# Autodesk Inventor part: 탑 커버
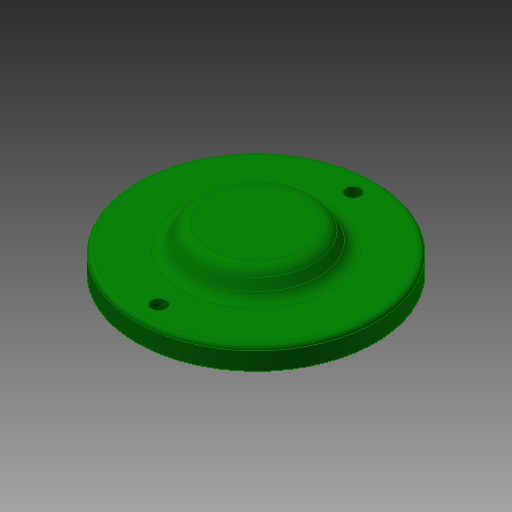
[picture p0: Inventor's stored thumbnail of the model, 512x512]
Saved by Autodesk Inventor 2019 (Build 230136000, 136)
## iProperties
Created: 2017-05
Part Number: 탑 커버
Material: 알루미늄 6061
Document SubType Name: Modeling
Designer: mduedu
Density: 1 g/cm^3
Appearance: 진녹색
Author: mduedu
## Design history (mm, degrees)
sketch "스케치1"
  geometry: C1 r 27 at (0, 0); 1 further point
  constraints: 1 centre point, 1 coincident
  dimensions: "d31" = 54 diameter of C1
extrude "돌출1" new body sketch "스케치1" distance "d2" = 5; taper "d3" = 0 deg
sketch "스케치2"
  geometry: C1 r 15 at (0, 0); 1 further point
  constraints: 1 centre point, 1 coincident
  dimensions: "d5" = 30 diameter of C1
extrude "돌출2" join sketch "스케치2" distance "d6" = 5; taper "d7" = -30 deg
sketch "스케치3"
  geometry: C1 r 16 at (0, 0); 1 further point
  constraints: 1 centre point, 1 coincident
  dimensions: "d32" = 32 diameter of C1
extrude "돌출3" join sketch "스케치3" distance "d10" = 3; taper "d11" = 0 deg
sketch "스케치4"
  geometry: C1 r 16 at (0, 0) reference; C2 r 13 at (0, 0); 1 further point
  constraints: 1 centre point
  dimensions: "d33" = 3 radial gap between concentric circles of C2 C1
extrude "돌출4" cut sketch "스케치4" distance "d14" = 6; taper "d15" = 0 deg
chamfer "모따기1" distance "d16" = 1; stored, may be unused: second distance "d17" = 2, angle "d18" = 45 deg
fillet "모깎기3" dims "d19" = 3
fillet "모깎기4" dims "d20" = 1
fillet "모깎기5" dims "d21" = 1
sketch "스케치5" dims "d34" = 44
  geometry: C1 r 27 at (0, 0) reference; 2 further points
  constraints: 2 vertical alignment, 1 coincident, 2 other
hole "구멍2" sketch "스케치5" at (0, 22) diameter "d35" = 3.4; stored, may be unused: countersink angle "d39" = 90 deg, drill point angle "d41" = 118 deg; dims "d36" = 6, "d37" = 4, "d38" = 2, "d40" = 8
node "솔리드1"
pattern_circular "원형 패턴1" dims angle "d43" = 360 deg
node "투영된 루프2"
